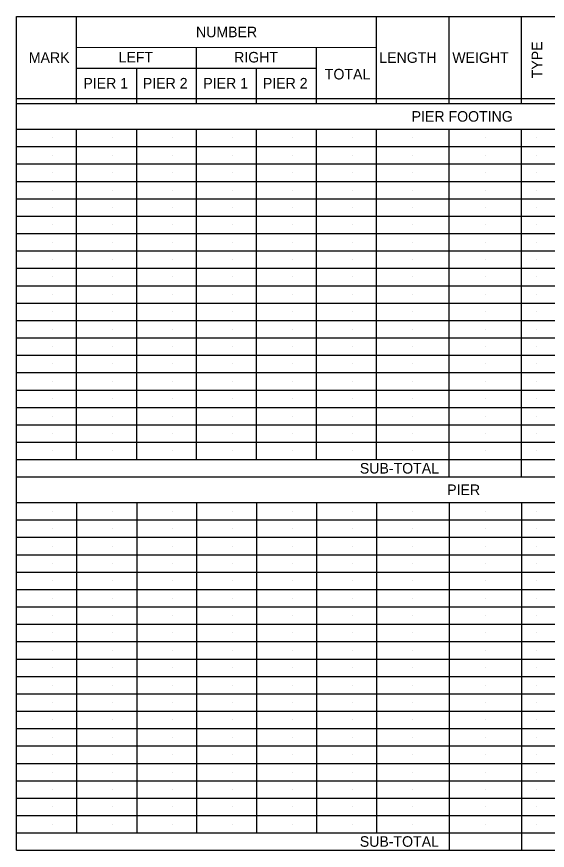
# Model space of a CAD drawing. Extents: x -18.5 to 33.3, y 0.6 to 37.5.
# Drawn here: x 10.02 to 18.57, y 24.12 to 37.54 of the extents above; entities that cross this region are included whole.
import ezdxf

# ---------------------------------------------------------------- set-up
doc = ezdxf.new("R2010")
doc.units = 0
doc.layers.add('BR_X_Beam_Centerline', color=7, linetype='Continuous')

msp = doc.modelspace()

# ---------------------------------------------------------------- linework, layer by layer
at = {"layer": 'BR_X_Beam_Centerline'}
for p, q in [((10.02, 37.539), (23.654, 37.539)), ((10.02, 24.115), (10.02, 37.539)), ((10.987, 36.138), (10.987, 37.539)), ((15.82, 36.138), (15.82, 37.539)), ((16.987, 36.139), (16.987, 37.539)), ((18.154, 36.139), (18.154, 37.539)), ((10.987, 37.045), (15.82, 37.044)), ((12.92, 36.138), (12.92, 37.045)), ((14.854, 36.138), (14.854, 37.044)), ((10.987, 36.712), (14.854, 36.712)), ((11.954, 36.139), (11.954, 36.712)), ((13.887, 36.138), (13.887, 36.712)), ((11.466, 36.467), (11.466, 36.467)), ((12.432, 36.467), (12.432, 36.467)), ((13.399, 36.467), (13.399, 36.467)), ((14.366, 36.467), (14.366, 36.467)), ((10.02, 36.221), (23.654, 36.221)), ((10.02, 36.139), (23.654, 36.139)), ((17.237, 35.933), (17.237, 35.933)), ((10.02, 35.727), (23.654, 35.727)), ((10.987, 30.407), (10.987, 35.727)), ((11.954, 30.407), (11.954, 35.727)), ((12.92, 30.407), (12.92, 35.727)), ((13.887, 30.407), (13.887, 35.727)), ((14.854, 30.407), (14.854, 35.727)), ((15.82, 30.407), (15.82, 35.727)), ((16.987, 30.127), (16.987, 35.727)), ((18.154, 30.127), (18.154, 35.727)), ((10.604, 35.587), (10.604, 35.587)), ((11.57, 35.587), (11.57, 35.587)), ((12.537, 35.587), (12.537, 35.587)), ((13.504, 35.587), (13.504, 35.587)), ((14.47, 35.587), (14.47, 35.587)), ((15.437, 35.587), (15.437, 35.587)), ((16.404, 35.587), (16.404, 35.587)), ((17.57, 35.587), (17.57, 35.587)), ((18.404, 35.587), (18.404, 35.587)), ((10.02, 35.447), (23.654, 35.447)), ((10.604, 35.307), (10.604, 35.307)), ((11.57, 35.307), (11.57, 35.307)), ((12.537, 35.307), (12.537, 35.307)), ((13.504, 35.307), (13.504, 35.307)), ((14.47, 35.307), (14.47, 35.307)), ((15.437, 35.307), (15.437, 35.307)), ((16.404, 35.307), (16.404, 35.307)), ((17.57, 35.307), (17.57, 35.307)), ((18.404, 35.307), (18.404, 35.307)), ((10.02, 35.167), (23.654, 35.167)), ((10.604, 35.027), (10.604, 35.027)), ((11.57, 35.027), (11.57, 35.027)), ((12.537, 35.027), (12.537, 35.027)), ((13.504, 35.027), (13.504, 35.027)), ((14.47, 35.027), (14.47, 35.027)), ((15.437, 35.027), (15.437, 35.027)), ((16.404, 35.027), (16.404, 35.027)), ((17.57, 35.027), (17.57, 35.027)), ((18.404, 35.027), (18.404, 35.027)), ((10.02, 34.887), (23.654, 34.887)), ((10.604, 34.747), (10.604, 34.747)), ((11.57, 34.747), (11.57, 34.747)), ((12.537, 34.747), (12.537, 34.747)), ((13.504, 34.747), (13.504, 34.747)), ((14.47, 34.747), (14.47, 34.747)), ((15.437, 34.747), (15.437, 34.747)), ((16.404, 34.747), (16.404, 34.747)), ((17.57, 34.747), (17.57, 34.747)), ((18.404, 34.747), (18.404, 34.747)), ((10.02, 34.607), (23.654, 34.607)), ((10.604, 34.467), (10.604, 34.467)), ((11.57, 34.467), (11.57, 34.467)), ((12.537, 34.467), (12.537, 34.467)), ((13.504, 34.467), (13.504, 34.467)), ((14.47, 34.467), (14.47, 34.467)), ((15.437, 34.467), (15.437, 34.467)), ((16.404, 34.467), (16.404, 34.467)), ((17.57, 34.467), (17.57, 34.467)), ((18.404, 34.467), (18.404, 34.467)), ((10.02, 34.327), (23.654, 34.327)), ((10.604, 34.187), (10.604, 34.187)), ((11.57, 34.187), (11.57, 34.187)), ((12.537, 34.187), (12.537, 34.187)), ((13.504, 34.187), (13.504, 34.187)), ((14.47, 34.187), (14.47, 34.187)), ((15.437, 34.187), (15.437, 34.187)), ((16.404, 34.187), (16.404, 34.187)), ((17.57, 34.187), (17.57, 34.187)), ((18.404, 34.187), (18.404, 34.187)), ((10.02, 34.047), (23.654, 34.047)), ((10.604, 33.907), (10.604, 33.907)), ((11.57, 33.907), (11.57, 33.907)), ((12.537, 33.907), (12.537, 33.907)), ((13.504, 33.907), (13.504, 33.907)), ((14.47, 33.907), (14.47, 33.907)), ((15.437, 33.907), (15.437, 33.907)), ((16.404, 33.907), (16.404, 33.907)), ((17.57, 33.907), (17.57, 33.907)), ((18.404, 33.907), (18.404, 33.907)), ((10.02, 33.767), (23.654, 33.767)), ((10.604, 33.627), (10.604, 33.627)), ((11.57, 33.627), (11.57, 33.627)), ((12.537, 33.627), (12.537, 33.627)), ((13.504, 33.627), (13.504, 33.627)), ((14.47, 33.627), (14.47, 33.627)), ((15.437, 33.627), (15.437, 33.627)), ((16.404, 33.627), (16.404, 33.627)), ((17.57, 33.627), (17.57, 33.627)), ((18.404, 33.627), (18.404, 33.627)), ((10.02, 33.487), (23.654, 33.487)), ((10.604, 33.347), (10.604, 33.347)), ((11.57, 33.347), (11.57, 33.347)), ((12.537, 33.347), (12.537, 33.347)), ((13.504, 33.347), (13.504, 33.347)), ((14.47, 33.347), (14.47, 33.347)), ((15.437, 33.347), (15.437, 33.347)), ((16.404, 33.347), (16.404, 33.347)), ((17.57, 33.347), (17.57, 33.347)), ((18.404, 33.347), (18.404, 33.347)), ((10.02, 33.207), (23.654, 33.207)), ((10.604, 33.067), (10.604, 33.067)), ((11.57, 33.067), (11.57, 33.067)), ((12.537, 33.067), (12.537, 33.067)), ((13.504, 33.067), (13.504, 33.067)), ((14.47, 33.067), (14.47, 33.067)), ((15.437, 33.067), (15.437, 33.067)), ((16.404, 33.067), (16.404, 33.067)), ((17.57, 33.067), (17.57, 33.067)), ((18.404, 33.067), (18.404, 33.067)), ((10.02, 32.927), (23.654, 32.927)), ((10.604, 32.787), (10.604, 32.787)), ((11.57, 32.787), (11.57, 32.787)), ((12.537, 32.787), (12.537, 32.787)), ((13.504, 32.787), (13.504, 32.787)), ((14.47, 32.787), (14.47, 32.787)), ((15.437, 32.787), (15.437, 32.787)), ((16.404, 32.787), (16.404, 32.787)), ((17.57, 32.787), (17.57, 32.787)), ((18.404, 32.787), (18.404, 32.787)), ((10.02, 32.647), (23.654, 32.647)), ((10.604, 32.507), (10.604, 32.507)), ((11.57, 32.507), (11.57, 32.507)), ((12.537, 32.507), (12.537, 32.507)), ((13.504, 32.507), (13.504, 32.507)), ((14.47, 32.507), (14.47, 32.507)), ((15.437, 32.507), (15.437, 32.507)), ((16.404, 32.507), (16.404, 32.507)), ((17.57, 32.507), (17.57, 32.507)), ((18.404, 32.507), (18.404, 32.507)), ((10.02, 32.367), (23.654, 32.367)), ((10.604, 32.227), (10.604, 32.227)), ((11.57, 32.227), (11.57, 32.227)), ((12.537, 32.227), (12.537, 32.227)), ((13.504, 32.227), (13.504, 32.227)), ((14.47, 32.227), (14.47, 32.227)), ((15.437, 32.227), (15.437, 32.227)), ((16.404, 32.227), (16.404, 32.227)), ((17.57, 32.227), (17.57, 32.227)), ((18.404, 32.227), (18.404, 32.227)), ((10.02, 32.087), (23.654, 32.087)), ((10.604, 31.947), (10.604, 31.947)), ((11.57, 31.947), (11.57, 31.947)), ((12.537, 31.947), (12.537, 31.947)), ((13.504, 31.947), (13.504, 31.947)), ((14.47, 31.947), (14.47, 31.947)), ((15.437, 31.947), (15.437, 31.947)), ((16.404, 31.947), (16.404, 31.947)), ((17.57, 31.947), (17.57, 31.947)), ((18.404, 31.947), (18.404, 31.947)), ((10.02, 31.807), (23.654, 31.807)), ((10.604, 31.667), (10.604, 31.667)), ((11.57, 31.667), (11.57, 31.667)), ((12.537, 31.667), (12.537, 31.667)), ((13.504, 31.667), (13.504, 31.667)), ((14.47, 31.667), (14.47, 31.667)), ((15.437, 31.667), (15.437, 31.667)), ((16.404, 31.667), (16.404, 31.667)), ((17.57, 31.667), (17.57, 31.667)), ((18.404, 31.667), (18.404, 31.667)), ((10.02, 31.527), (23.654, 31.527)), ((10.604, 31.387), (10.604, 31.387)), ((11.57, 31.387), (11.57, 31.387)), ((12.537, 31.387), (12.537, 31.387)), ((13.504, 31.387), (13.504, 31.387)), ((14.47, 31.387), (14.47, 31.387)), ((15.437, 31.387), (15.437, 31.387)), ((16.404, 31.387), (16.404, 31.387)), ((17.57, 31.387), (17.57, 31.387)), ((18.404, 31.387), (18.404, 31.387)), ((10.02, 31.247), (23.654, 31.247)), ((10.604, 31.107), (10.604, 31.107)), ((11.57, 31.107), (11.57, 31.107)), ((12.537, 31.107), (12.537, 31.107)), ((13.504, 31.107), (13.504, 31.107)), ((14.47, 31.107), (14.47, 31.107)), ((15.437, 31.107), (15.437, 31.107)), ((16.404, 31.107), (16.404, 31.107)), ((17.57, 31.107), (17.57, 31.107)), ((18.404, 31.107), (18.404, 31.107)), ((10.02, 30.967), (23.654, 30.967)), ((10.604, 30.827), (10.604, 30.827)), ((11.57, 30.827), (11.57, 30.827)), ((12.537, 30.827), (12.537, 30.827)), ((13.504, 30.827), (13.504, 30.827)), ((14.47, 30.827), (14.47, 30.827)), ((15.437, 30.827), (15.437, 30.827)), ((16.404, 30.827), (16.404, 30.827)), ((17.57, 30.827), (17.57, 30.827)), ((18.404, 30.827), (18.404, 30.827)), ((10.02, 30.687), (23.654, 30.687)), ((10.604, 30.547), (10.604, 30.547)), ((11.57, 30.547), (11.57, 30.547)), ((12.537, 30.547), (12.537, 30.547)), ((13.504, 30.547), (13.504, 30.547)), ((14.47, 30.547), (14.47, 30.547)), ((15.437, 30.547), (15.437, 30.547)), ((16.404, 30.547), (16.404, 30.547)), ((17.57, 30.547), (17.57, 30.547)), ((18.404, 30.547), (18.404, 30.547)), ((10.02, 30.407), (23.654, 30.407)), ((10.02, 30.127), (23.654, 30.127)), ((17.237, 29.921), (17.237, 29.921)), ((10.02, 29.715), (23.654, 29.715)), ((10.987, 29.715), (10.987, 24.395)), ((11.954, 29.715), (11.954, 24.395)), ((12.92, 29.715), (12.92, 24.395)), ((13.887, 29.715), (13.887, 24.395)), ((14.854, 29.715), (14.854, 24.395)), ((15.82, 29.715), (15.82, 24.395)), ((16.987, 29.715), (16.987, 24.115)), ((18.154, 29.715), (18.154, 24.115)), ((10.604, 29.575), (10.604, 29.575)), ((11.57, 29.575), (11.57, 29.575)), ((12.537, 29.575), (12.537, 29.575)), ((13.504, 29.575), (13.504, 29.575)), ((14.47, 29.575), (14.47, 29.575)), ((15.437, 29.575), (15.437, 29.575)), ((16.404, 29.575), (16.404, 29.575)), ((17.57, 29.575), (17.57, 29.575)), ((18.404, 29.575), (18.404, 29.575)), ((10.02, 29.435), (23.654, 29.435)), ((10.604, 29.295), (10.604, 29.295)), ((11.57, 29.295), (11.57, 29.295)), ((12.537, 29.295), (12.537, 29.295)), ((13.504, 29.295), (13.504, 29.295)), ((14.47, 29.295), (14.47, 29.295)), ((15.437, 29.295), (15.437, 29.295)), ((16.404, 29.295), (16.404, 29.295)), ((17.57, 29.295), (17.57, 29.295)), ((18.404, 29.295), (18.404, 29.295)), ((10.02, 29.155), (23.654, 29.155)), ((10.604, 29.015), (10.604, 29.015)), ((11.57, 29.015), (11.57, 29.015)), ((12.537, 29.015), (12.537, 29.015)), ((13.504, 29.015), (13.504, 29.015)), ((14.47, 29.015), (14.47, 29.015)), ((15.437, 29.015), (15.437, 29.015)), ((16.404, 29.015), (16.404, 29.015)), ((17.57, 29.015), (17.57, 29.015)), ((18.404, 29.015), (18.404, 29.015)), ((10.02, 28.875), (23.654, 28.875)), ((10.604, 28.735), (10.604, 28.735)), ((11.57, 28.735), (11.57, 28.735)), ((12.537, 28.735), (12.537, 28.735)), ((13.504, 28.735), (13.504, 28.735)), ((14.47, 28.735), (14.47, 28.735)), ((15.437, 28.735), (15.437, 28.735)), ((16.404, 28.735), (16.404, 28.735)), ((17.57, 28.735), (17.57, 28.735)), ((18.404, 28.735), (18.404, 28.735)), ((10.02, 28.595), (23.654, 28.595)), ((10.604, 28.455), (10.604, 28.455)), ((11.57, 28.455), (11.57, 28.455)), ((12.537, 28.455), (12.537, 28.455)), ((13.504, 28.455), (13.504, 28.455)), ((14.47, 28.455), (14.47, 28.455)), ((15.437, 28.455), (15.437, 28.455)), ((16.404, 28.455), (16.404, 28.455)), ((17.57, 28.455), (17.57, 28.455)), ((18.404, 28.455), (18.404, 28.455)), ((10.02, 28.315), (23.654, 28.315)), ((10.604, 28.175), (10.604, 28.175)), ((11.57, 28.175), (11.57, 28.175)), ((12.537, 28.175), (12.537, 28.175)), ((13.504, 28.175), (13.504, 28.175)), ((14.47, 28.175), (14.47, 28.175)), ((15.437, 28.175), (15.437, 28.175)), ((16.404, 28.175), (16.404, 28.175)), ((17.57, 28.175), (17.57, 28.175)), ((18.404, 28.175), (18.404, 28.175)), ((10.02, 28.035), (23.654, 28.035)), ((10.604, 27.895), (10.604, 27.895)), ((11.57, 27.895), (11.57, 27.895)), ((12.537, 27.895), (12.537, 27.895)), ((13.504, 27.895), (13.504, 27.895)), ((14.47, 27.895), (14.47, 27.895)), ((15.437, 27.895), (15.437, 27.895)), ((16.404, 27.895), (16.404, 27.895)), ((17.57, 27.895), (17.57, 27.895)), ((18.404, 27.895), (18.404, 27.895)), ((10.02, 27.755), (23.654, 27.755)), ((10.604, 27.615), (10.604, 27.615)), ((11.57, 27.615), (11.57, 27.615)), ((12.537, 27.615), (12.537, 27.615)), ((13.504, 27.615), (13.504, 27.615)), ((14.47, 27.615), (14.47, 27.615)), ((15.437, 27.615), (15.437, 27.615)), ((16.404, 27.615), (16.404, 27.615)), ((17.57, 27.615), (17.57, 27.615)), ((18.404, 27.615), (18.404, 27.615)), ((10.02, 27.475), (23.654, 27.475)), ((10.604, 27.335), (10.604, 27.335)), ((11.57, 27.335), (11.57, 27.335)), ((12.537, 27.335), (12.537, 27.335)), ((13.504, 27.335), (13.504, 27.335)), ((14.47, 27.335), (14.47, 27.335)), ((15.437, 27.335), (15.437, 27.335)), ((16.404, 27.335), (16.404, 27.335)), ((17.57, 27.335), (17.57, 27.335)), ((18.404, 27.335), (18.404, 27.335)), ((10.02, 27.195), (23.654, 27.195)), ((10.604, 27.055), (10.604, 27.055)), ((11.57, 27.055), (11.57, 27.055)), ((12.537, 27.055), (12.537, 27.055)), ((13.504, 27.055), (13.504, 27.055)), ((14.47, 27.055), (14.47, 27.055)), ((15.437, 27.055), (15.437, 27.055)), ((16.404, 27.055), (16.404, 27.055)), ((17.57, 27.055), (17.57, 27.055)), ((18.404, 27.055), (18.404, 27.055)), ((10.02, 26.915), (23.654, 26.915)), ((10.604, 26.775), (10.604, 26.775)), ((11.57, 26.775), (11.57, 26.775)), ((12.537, 26.775), (12.537, 26.775)), ((13.504, 26.775), (13.504, 26.775)), ((14.47, 26.775), (14.47, 26.775)), ((15.437, 26.775), (15.437, 26.775)), ((16.404, 26.775), (16.404, 26.775)), ((17.57, 26.775), (17.57, 26.775)), ((18.404, 26.775), (18.404, 26.775)), ((10.02, 26.635), (23.654, 26.635)), ((10.604, 26.495), (10.604, 26.495)), ((11.57, 26.495), (11.57, 26.495)), ((12.537, 26.495), (12.537, 26.495)), ((13.504, 26.495), (13.504, 26.495)), ((14.47, 26.495), (14.47, 26.495)), ((15.437, 26.495), (15.437, 26.495)), ((16.404, 26.495), (16.404, 26.495)), ((17.57, 26.495), (17.57, 26.495)), ((18.404, 26.495), (18.404, 26.495)), ((10.02, 26.355), (23.654, 26.355)), ((10.604, 26.215), (10.604, 26.215)), ((11.57, 26.215), (11.57, 26.215)), ((12.537, 26.215), (12.537, 26.215)), ((13.504, 26.215), (13.504, 26.215)), ((14.47, 26.215), (14.47, 26.215)), ((15.437, 26.215), (15.437, 26.215)), ((16.404, 26.215), (16.404, 26.215)), ((17.57, 26.215), (17.57, 26.215)), ((18.404, 26.215), (18.404, 26.215)), ((10.02, 26.075), (23.654, 26.075)), ((10.604, 25.935), (10.604, 25.935)), ((11.57, 25.935), (11.57, 25.935)), ((12.537, 25.935), (12.537, 25.935)), ((13.504, 25.935), (13.504, 25.935)), ((14.47, 25.935), (14.47, 25.935)), ((15.437, 25.935), (15.437, 25.935)), ((16.404, 25.935), (16.404, 25.935)), ((17.57, 25.935), (17.57, 25.935)), ((18.404, 25.935), (18.404, 25.935)), ((10.02, 25.795), (23.654, 25.795)), ((10.604, 25.655), (10.604, 25.655)), ((11.57, 25.655), (11.57, 25.655)), ((12.537, 25.655), (12.537, 25.655)), ((13.504, 25.655), (13.504, 25.655)), ((14.47, 25.655), (14.47, 25.655)), ((15.437, 25.655), (15.437, 25.655)), ((16.404, 25.655), (16.404, 25.655)), ((17.57, 25.655), (17.57, 25.655)), ((18.404, 25.655), (18.404, 25.655)), ((10.02, 25.515), (23.654, 25.515)), ((10.604, 25.375), (10.604, 25.375)), ((11.57, 25.375), (11.57, 25.375)), ((12.537, 25.375), (12.537, 25.375)), ((13.504, 25.375), (13.504, 25.375)), ((14.47, 25.375), (14.47, 25.375)), ((15.437, 25.375), (15.437, 25.375)), ((16.404, 25.375), (16.404, 25.375)), ((17.57, 25.375), (17.57, 25.375)), ((18.404, 25.375), (18.404, 25.375)), ((10.02, 25.235), (23.654, 25.235)), ((10.604, 25.095), (10.604, 25.095)), ((11.57, 25.095), (11.57, 25.095)), ((12.537, 25.095), (12.537, 25.095)), ((13.504, 25.095), (13.504, 25.095)), ((14.47, 25.095), (14.47, 25.095)), ((15.437, 25.095), (15.437, 25.095)), ((16.404, 25.095), (16.404, 25.095)), ((17.57, 25.095), (17.57, 25.095)), ((18.404, 25.095), (18.404, 25.095)), ((10.02, 24.955), (23.654, 24.955)), ((10.604, 24.815), (10.604, 24.815)), ((11.57, 24.815), (11.57, 24.815)), ((12.537, 24.815), (12.537, 24.815)), ((13.504, 24.815), (13.504, 24.815)), ((14.47, 24.815), (14.47, 24.815)), ((15.437, 24.815), (15.437, 24.815)), ((16.404, 24.815), (16.404, 24.815)), ((17.57, 24.815), (17.57, 24.815)), ((18.404, 24.815), (18.404, 24.815)), ((10.02, 24.675), (23.654, 24.675)), ((10.604, 24.535), (10.604, 24.535)), ((11.57, 24.535), (11.57, 24.535)), ((12.537, 24.535), (12.537, 24.535)), ((13.504, 24.535), (13.504, 24.535)), ((14.47, 24.535), (14.47, 24.535)), ((15.437, 24.535), (15.437, 24.535)), ((16.404, 24.535), (16.404, 24.535)), ((17.57, 24.535), (17.57, 24.535)), ((18.404, 24.535), (18.404, 24.535)), ((10.02, 24.395), (23.654, 24.395)), ((10.02, 24.115), (23.654, 24.115))]:
    msp.add_line(p, q, dxfattribs=at)

# ---------------------------------------------------------------- texts
for s, p in [('NUMBER', (12.91, 37.207)), ('MARK', (10.216, 36.795)), ('LEFT', (11.663, 36.801)), ('RIGHT', (13.524, 36.801)), ('LENGTH', (15.864, 36.795)), ('WEIGHT', (17.04, 36.795)), ('TOTAL', (14.986, 36.528)), ('PIER 1', (11.095, 36.382)), ('PIER 2', (12.054, 36.382)), ('PIER 1', (13.028, 36.382)), ('PIER 2', (13.988, 36.382)), ('PIER FOOTING', (16.385, 35.848)), ('SUB-TOTAL', (15.55, 30.182)), ('PIER', (16.958, 29.836)), ('SUB-TOTAL', (15.549, 24.172))]:
    msp.add_text(s, height=0.17, dxfattribs=at).set_placement(p)
msp.add_text('TYPE', height=0.17, rotation=90, dxfattribs=at).set_placement((18.489, 36.546))

doc.saveas('drawing.dxf')
